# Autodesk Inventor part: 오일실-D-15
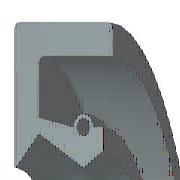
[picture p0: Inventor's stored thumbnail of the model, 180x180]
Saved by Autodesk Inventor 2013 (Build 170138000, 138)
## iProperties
IsCustomPart: 0
Company: 한국ATC센터
Created: 2014-12
Part Number: 오일실-D-15
Material: 고무
Description: 오일-실
Document SubType Name: Modeling
Standard: KS B 2804
Designer: KYOUNG IL JANG
Standards Organization: KS
Language: ko-KR
Size Designation: D - 15 30 7
Categories: <MemberInstance><Categories><Category DisplayName="샤프트 부품" InternalName="7f7aeb1f-a693-4053-b835-cee3144e0d98" Mnemonic="SHFT"><Category DisplayName="실링" Intern
Density: 0.93 g/cm^3
Mass: 1.95008 g
Surface Area: 27.8517 cm^2
Volume: 2.09686 cm^3
Author: KYOUNG IL JANG
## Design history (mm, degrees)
revolve "본체" stored, may be unused: angle "d17" = 90 deg
revolve "스프링1" stored, may be unused: angle "d18" = 90 deg
body "Solid1"
sketch "스케치1"
  geometry: L1 (0, 15)-(7, 15); L2 (7, 13.25)-(1.75, 13.25); L3 (1.75, 9.25)-(4.9, 7.5); L4 (4.9, 7.5)-(0, 7.5); L5 (0, 0)-(9.586, 0) reference; L6 (4.9, 7.5)-(6.3, 8.375); L7 (0, 18)-(0, -3) reference; L8 (-1.941, 0)-(11.507, 0) reference; L9 (4.2, 9.6)-(1.75, 10.09); L10 (1.75, 10.09)-(1.75, 13.25); L11 (0, 15)-(0, 7.588); L12 (4.9, 7.5)-(0, 7.5); L13 (1.75, 9.25)-(0.152, 7.528); L14 (7, 15)-(7, 13.25); L15 (5.6, 9.6)-(6.3, 9.6); L16 (6.3, 9.6)-(6.3, 8.375); C1 r 0.455 at (4.9, 9.6); A1 r 0.7 centre (4.9, 9.6) between (5.6, 9.6) and (4.2, 9.6); A2 r 0.088 centre (0.088, 7.588) between (0, 7.588) and (0.152, 7.528); 1 further point
  constraints: 28 end point, 5 horizontal alignment, 5 point on line, 4 point on circle, 4 vertical alignment, 3 centre point, 3 tangent, 2 collinear, 2 horizontal, 2 perpendicular, 1 coincident, 1 parallel
  dimensions: "d0" = 30 diameter of L1 L5 (= SD2); "d1" = 1.75 distance of L1.end L2.start (= SD); "d2" = 0.91 diameter of C1 (= SPDI); "d3" = 1.4 diameter of A1 (= SPDA); "d4" = 15 diameter of L3.end L5 (= NND); "d5" = 18.5 diameter of L3.start L5 (= TKDM); "d7" = 20.18 diameter of L9.end L5 (= TKDM + 0.24 x SWDT); "d8" = 1.75 distance between parallel lines of L11 L10 (= SD); "d9" = 4.9 distance from line of L11 C1.centre (= SPDST); "d10" = 19.2 diameter of C1.centre L5 (= HLDM); "d11" = 0.0875 radius of A2 (= 0.25 x LAB); "d12" = 6.3 distance between parallel lines of L11 L16 (= SDI); "d13" = 16.75 diameter of L6.end L5 (= ABDM); "d14" = 7 distance from line of L11 L1.end (= SWDT)
fillet "모깎기1" dims "d6" = 0.3 (= RR)
other parameters: "SD2" = 30 [user parameter; used in 1 equation term], "SWDT" = 7 [user parameter; used in 2 equation terms], "RR" = 0.3 [user parameter; used in 1 equation term], "SD" = 1.75 [user parameter; used in 2 equation terms], "NND" = 15 [user parameter; used in 1 equation term], "SPDA" = 1.4 [user parameter; used in 1 equation term], "SPDI" = 0.91 [user parameter; used in 1 equation term], "TKDM" = 18.5 [user parameter; used in 2 equation terms], "HLDM" = 19.2 [user parameter; used in 1 equation term], "ABDM" = 16.75 [user parameter; used in 1 equation term], "SDI" = 6.3 [user parameter; used in 1 equation term], "SPDST" = 4.9 [user parameter; used in 1 equation term], "LAB" = 0.35 [user parameter; used in 1 equation term], "d15" = 0, "d16" = 0, "d19" = 0
